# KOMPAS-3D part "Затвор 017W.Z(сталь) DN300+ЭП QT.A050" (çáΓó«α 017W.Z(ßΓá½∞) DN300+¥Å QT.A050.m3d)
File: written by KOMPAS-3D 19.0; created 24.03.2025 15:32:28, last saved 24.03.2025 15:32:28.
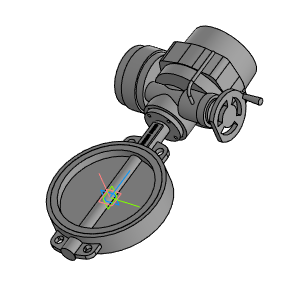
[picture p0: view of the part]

Document properties: Полное имя файла: Затвор 017W.Z(сталь) DN300+ЭП QT.A050.a3d

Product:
- Part/product: Затвор 017W.Z(сталь) DN300+ЭП QT.A050
    Масса: 152.543

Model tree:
1. Операция без истории:1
